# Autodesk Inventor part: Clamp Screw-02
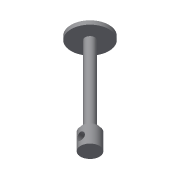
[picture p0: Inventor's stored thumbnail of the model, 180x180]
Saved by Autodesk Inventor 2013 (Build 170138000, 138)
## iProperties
Created: 2002-02
Part Number: Clamp Screw-02
Material: Generic
Document SubType Name: Modeling
Designer: ***
Density: 1 g/cm^3
Author: ***
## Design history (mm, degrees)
derived "Clamp Screw.ipt"
feature "Solid1::Clamp Screw.ipt"
tag "TaggingFeature1"
body "Solid1"
other parameters: "d2" = 13, "d4" = 25, "d5" = 3, "d6" = 8, "d7" = 13, "d8" = 22, "d10" = 102, "d14" = 11, "d16" = 0
